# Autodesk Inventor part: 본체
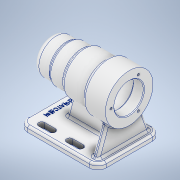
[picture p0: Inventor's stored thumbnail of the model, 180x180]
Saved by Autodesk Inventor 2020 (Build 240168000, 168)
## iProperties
Created: 2021-10
Part Number: 본체
Material: 알루미늄 6061
Document SubType Name: Modeling
Designer: user
Density: 2.7 g/cm^3
Appearance: 알루미늄 - 평지
Mass: 690.77 g
Surface Area: 699.78 cm^2
Volume: 255.841 cm^3
Author: user
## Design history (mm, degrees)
sketch "스케치1"
  geometry: L1 (0, 0)-(112, 0); L2 (0, 0)-(0, 25); L3 (0, 25)-(24, 25); L4 (24, 25)-(24, 27); L5 (24, 27)-(46, 27); L6 (46, 27)-(46, 30); L7 (46, 30)-(80, 30); L8 (80, 30)-(80, 34); L9 (80, 34)-(112, 34); L10 (112, 34)-(112, 0)
  constraints: 20 end point, 8 perpendicular, 1 horizontal, 1 vertical
  dimensions: "d0" = 112 distance of L1.start L1.end; "d1" = 50 diameter of L3 L1; "d2" = 54 diameter of L5 L1; "d3" = 60 diameter of L7 L1; "d4" = 68 diameter of L9 L1; "d5" = 24 distance from line of L2 L4.end; "d6" = 46 distance from line of L2 L6.end; "d7" = 80 distance from line of L2 L8.end
revolve "회전1" sketch "스케치1" stored, may be unused: angle "d8" = 90 deg
sketch "스케치2"
  geometry: 1 further point
hole "구멍1" sketch "스케치2" at (0, 0) diameter "d9" = 42; stored, may be unused: countersink angle "d13" = 90 deg, drill point angle "d15" = 0 deg; dims "d10" = 8, "d11" = 4, "d12" = 2, "d14" = 15
sketch "스케치3"
  geometry: 1 further point
hole "구멍2" sketch "스케치3" at (0, 0) diameter "d16" = 48; stored, may be unused: countersink angle "d20" = 90 deg, drill point angle "d22" = 0 deg; dims "d17" = 8, "d18" = 4, "d19" = 2, "d21" = 54
sketch "스케치4"
  geometry: 1 further point
hole "구멍3" sketch "스케치4" at (0, 0) diameter "d23" = 42; stored, may be unused: countersink angle "d27" = 90 deg, drill point angle "d29" = 0 deg; dims "d24" = 8, "d25" = 4, "d26" = 2, "d28" = 12
sketch "스케치5"
  geometry: 1 further point
hole "구멍4" sketch "스케치5" at (0, 0) diameter "d30" = 35; stored, may be unused: countersink angle "d34" = 90 deg, drill point angle "d36" = 0 deg; dims "d31" = 8, "d32" = 4, "d33" = 2, "d35" = 18
sketch "스케치6"
  geometry: 1 further point
hole "구멍5" sketch "스케치6" at (0, 0) diameter "d37" = 32; stored, may be unused: countersink angle "d41" = 90 deg, drill point angle "d43" = 0 deg; dims "d38" = 8, "d39" = 4, "d40" = 2, "d42" = 4
sketch "스케치7"
  geometry: 1 further point
hole "구멍6" sketch "스케치7" at (0, 0) diameter "d44" = 21; stored, may be unused: countersink angle "d48" = 90 deg, drill point angle "d50" = 0 deg; dims "d45" = 8, "d46" = 4, "d47" = 2, "d49" = 3
node "작업 평면1"
sketch "스케치8"
  geometry: L1 (0, -45)-(-112, -45); L2 (-112, -45)-(-112, 45); L3 (-112, 45)-(0, 45); L4 (0, 45)-(0, -45); L5 (0, -45)-(-112, 45); L6 (-112, -45)-(0, 45); 3 further points
  constraints: 12 end point, 3 midpoint, 2 parallel, 1 coincident, 1 horizontal, 1 perpendicular
  dimensions: "d52" = 112 distance of L1.start L1.end; "d53" = 90 distance of L1.end L2.end
extrude "돌출1" join sketch "스케치8" distance "d54" = 8; taper "d55" = 0 deg
node "작업 평면2"
sketch "스케치9"
  geometry: L1 (-24.658, 23.409)-(-62, 37); L2 (-70, 45)-(-62, 45) reference; L3 (-62, -45)-(-62, 45) reference; 2 further points
  constraints: 2 end point, 1 point on line, 2 other
  dimensions: "d57" = 8 distance from line of L2 L1.end; "d58" = 110 deg angle of L3 L1
feature "리브1" sketch "스케치9" dims "d59" = 40, "d60" = 8, "d61" = 0, "d62" = 0, "d63" = 1, "d64" = 1
sketch "스케치10"
  geometry: L1 (36.378, -27)-(27, -62); L2 (0, -70)-(0, -62) reference; L3 (112, -62)-(0, -62) reference; L4 (24, -27)-(46, -27) reference; 1 further point
  constraints: 2 end point, 2 point on line
  dimensions: "d65" = 27 distance from line of L2 L1.end; "d66" = 105 deg angle of L3 L1
feature "리브2" sketch "스케치10" dims "d67" = 30, "d68" = 8, "d69" = 0, "d70" = 0, "d71" = 1, "d72" = 1
fillet "모깎기1" dims "d73" = 12
sketch "스케치11"
  geometry: L1 (20, -33)-(35, -33); L2 (20, -37.5)-(35, -37.5); L3 (35, -28.5)-(20, -28.5); L4 (60, -33)-(75, -33); L5 (60, -28.5)-(75, -28.5); L6 (75, -37.5)-(60, -37.5); L7 (0, 33)-(0, -33) reference; A1 r 4.5 centre (20, -33) between (20, -28.5) and (20, -37.5); A2 r 4.5 centre (35, -33) between (35, -37.5) and (35, -28.5); A3 r 4.5 centre (60, -33) between (60, -28.5) and (60, -37.5); A4 r 4.5 centre (75, -33) between (75, -37.5) and (75, -28.5); 3 further points
  constraints: 16 end point, 8 point on circle, 8 tangent, 4 centre point, 2 horizontal, 2 midpoint, 2 parallel
  dimensions: "d74" = 15 distance of L1.end L1.start; "d75" = 15 distance of L4.end L4.start; "d76" = 9 distance between parallel lines of L2 L3; "d77" = 9 distance between parallel lines of L6 L5; "d78" = 20 distance from line of L7 L1.start; "d79" = 25 distance of L4.start L1.end; "d80" = 33 vertical distance of L1.start point (0, 0); "d81" = 33 vertical distance of point (0, 0) L4.start
extrude "돌출2" cut sketch "스케치11" extent not by distance; stored distance "d82" = 0; taper "d83" = 0 deg
sketch "스케치12"
  geometry: 2 further points
  constraints: 1 horizontal alignment
  dimensions: "d84" = 26 distance of point (-26, 0) point (0, 0)
hole "구멍7" sketch "스케치12" at (-26, 0) diameter "d85" = 3.242; stored, may be unused: countersink angle "d89" = 90 deg, drill point angle "d91" = 118 deg; dims "d86" = 8, "d87" = 4, "d88" = 2, "d90" = 11
fillet "모깎기2" dims "d95" = 8
fillet "모깎기3" dims "d96" = 3
fillet "모깎기4" dims "d97" = 3
fillet "모깎기5" dims "d98" = 0.3
fillet "모깎기6" dims "d99" = 3
chamfer "모따기1" distance "d100" = 1; stored, may be unused: second distance "d101" = 2, angle "d102" = 45 deg
fillet "모깎기7" dims "d103" = 3
fillet "모깎기8" dims "d104" = 3
fillet "모깎기9" dims "d105" = 3
fillet "모깎기10" dims "d106" = 3
sketch "스케치13"
  geometry: L1 (0, 33)-(0, -33) reference; A1 r 4.5 centre (20, 33) between (20, 37.5) and (20, 28.5) reference; 2 further points
  constraints: 1 other
  dimensions: "d107" = 12 distance from line of L1 point (12, 0); "d108" = 33 vertical distance of point (12, 0) A1.centre
feature "엠보싱1" sketch "스케치13" dims "d18" = 4, "d109" = 0.5, "d110" = 0
fillet "모깎기11" dims "d111" = 3
node "솔리드1"
mirror "미러1"
mirror "미러2"
pattern_circular "원형 패턴1" dims angle "d93" = 360 deg
feature "A9D066F2-1C7D-4E18-AEED-F7BC21143FA4" dims "d9" = 42, "d10" = 8, "d11" = 4, "d12" = 2, "d13" = 90 deg, "d14" = 15, "d15" = 0
other parameters: "d56" = 104
